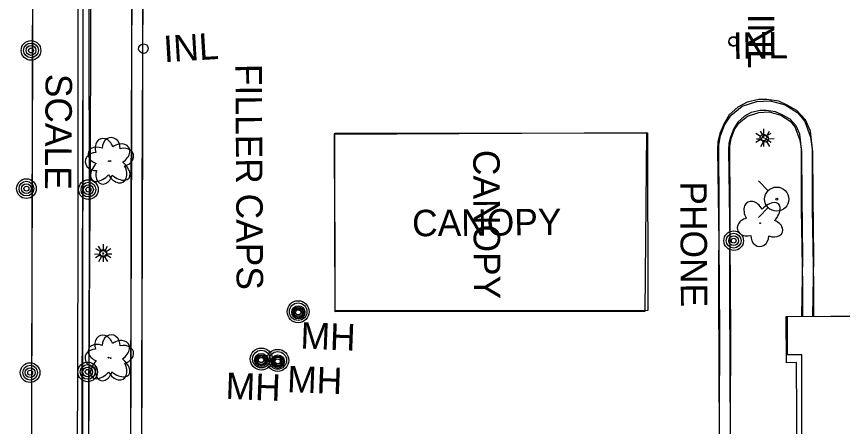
# Model space of a CAD drawing. Extents: x 588843 to 2552415, y 180129 to 269402.
# Drawn here: x 594396.9 to 594584.3, y 184767.3 to 184860.3 of the extents above; entities that cross this region are included whole.
import ezdxf

# ---------------------------------------------------------------- set-up
doc = ezdxf.new("R2010")
doc.units = 0
for name, color, linetype in [('Default', 7, 'Continuous'), ('E_BLD', 7, 'Continuous'), ('E_BLD_Dash', 7, 'Continuous'), ('E_BLD_HvyDash', 7, 'Continuous'), ('E_BLD_Text', 7, 'Continuous'), ('E_DRN', 7, 'Continuous'), ('E_DRN_Text', 7, 'Continuous'), ('E_DWY', 7, 'Continuous'), ('E_LAND_Vegetation', 7, 'Continuous'), ('E_LTG', 7, 'Continuous'), ('E_MISCPROP', 7, 'Continuous'), ('E_MISCPROP_Text', 7, 'Continuous'), ('E_UTL_AG_Text', 7, 'Continuous'), ('E_UTL_MH', 7, 'Continuous'), ('E_UTL_MH_Text', 7, 'Continuous'), ('E_UTL_WHydrant', 7, 'Continuous')]:
    doc.layers.add(name, color=color, linetype=linetype)

# ---------------------------------------------------------------- blocks, each defined once
blk = doc.blocks.new('SCAL')
at = {"layer": 'Default'}
blk.add_text('SCALE', height=12, dxfattribs=at).set_placement((-23.24, -6))
blk = doc.blocks.new('POLE')
at = {"layer": 'Default'}
for radius in [4.46, 3.35, 2.23, 1.12]:
    blk.add_circle((0, 0), radius, dxfattribs=at)
blk = doc.blocks.new('LPOL')
at = {"layer": 'Default'}
for p, q in [((-4, 0), (-1.5, 0)), ((-0.75, 1.3), (-2, 3.46)), ((0.75, 1.3), (2, 3.46)), ((1.5, 0), (4, 0)), ((-2, -3.46), (-0.75, -1.3)), ((2, -3.46), (0.75, -1.3))]:
    blk.add_line(p, q, dxfattribs=at)
for radius in [1.5, 1.5, 1.5, 0.125]:
    blk.add_circle((0, 0), radius, dxfattribs=at)
blk = doc.blocks.new('DTRE')
at = {"layer": 'Default'}
blk.add_circle((-0.18, 0), 0.183, dxfattribs=at)
for centre, major_axis, ratio in [((-1.87, 5.32), (1.36, -4.98), 0.782863), ((4.06, 2.74), (-5.27, -2.93), 0.691916), ((-5.87, 0.15), (4.93, -0.12), 0.832022), ((3.54, -3.71), (-5.01, 4.58), 0.560249), ((-2.49, -5.24), (1.8, 4.86), 0.716896)]:
    blk.add_ellipse(centre, major_axis=major_axis, ratio=ratio, start_param=1.570796, end_param=4.712389, dxfattribs=at)
blk = doc.blocks.new('CANOPY')
at = {"layer": 'E_BLD_Text'}
blk.add_text('CANOPY', height=12, dxfattribs=at).set_placement((-32.52, -6))
blk = doc.blocks.new('FILO')
at = {"layer": 'E_MISCPROP'}
for radius in [5, 4, 1.5]:
    blk.add_circle((0, 0), radius, dxfattribs=at)
blk = doc.blocks.new('FILT_4')
at = {"layer": 'E_MISCPROP_Text'}
blk.add_text('FILLER CAPS', height=12, dxfattribs=at).set_placement((10, -6))
blk = doc.blocks.new('PHONE')
at = {"layer": 'E_UTL_AG_Text'}
blk.add_text('PHONE', height=12, dxfattribs=at).set_placement((-26.35, -6))
blk = doc.blocks.new('HYD')
at = {"layer": 'Default'}
for p, q in [((-3.84, 3.84), (-8.32, 8.32)), ((3.84, 3.84), (8.32, 8.32))]:
    blk.add_line(p, q, dxfattribs=at)
for radius in [5.48, 0.42]:
    blk.add_circle((0, 0), radius, dxfattribs=at)
blk = doc.blocks.new('INLT_51')
at = {"layer": 'E_DRN_Text'}
blk.add_text('INL', height=12, dxfattribs=at).set_placement((-11.03, -6))
blk = doc.blocks.new('LPOL_4')
at = {"layer": 'E_LTG'}
for p, q in [((-13.1, 0), (-4.9, 0)), ((-2.5, 4.3), (-6.6, 11.4)), ((2.5, 4.3), (6.6, 11.4)), ((4.9, 0), (13.1, 0)), ((-6.6, -11.4), (-2.5, -4.3)), ((6.6, -11.4), (2.5, -4.3))]:
    blk.add_line(p, q, dxfattribs=at)
for radius in [4.92, 4.92, 4.92, 0.41]:
    blk.add_circle((0, 0), radius, dxfattribs=at)
blk = doc.blocks.new('INLT_32_2')
at = {"layer": 'E_DRN_Text'}
blk.add_text('INL', height=39.37, dxfattribs=at).set_placement((-36.2, -19.7))
blk = doc.blocks.new('MHO_3')
at = {"layer": 'E_UTL_MH'}
for centre, radius in [((0.3, -0.4), 9.84), ((0.3, -0.4), 7.98), ((0.2, -0.5), 6.35), ((0.1, -0.5), 3.97)]:
    blk.add_circle(centre, radius, dxfattribs=at)
blk = doc.blocks.new('MHT_3')
at = {"layer": 'E_UTL_MH_Text'}
blk.add_text('MH', height=39.37, dxfattribs=at).set_placement((-32.2, -19.7))
blk = doc.blocks.new('DTRE_4')
at = {"layer": 'E_LAND_Vegetation'}
blk.add_circle((-0.6, 0), 0.601, dxfattribs=at)
for centre, major_axis, ratio in [((-6.1, 17.5), (4.5, -16.3), 0.782863), ((13.3, 9), (-17.3, -9.6), 0.691916), ((-19.3, 0.5), (16.2, -0.4), 0.832022), ((11.6, -12.2), (-16.4, 15), 0.560249), ((-8.2, -17.2), (5.9, 15.9), 0.716896)]:
    blk.add_ellipse(centre, major_axis=major_axis, ratio=ratio, start_param=1.570796, end_param=4.712389, dxfattribs=at)
blk = doc.blocks.new('INLT_24_2')
at = {"layer": 'E_DRN_Text'}
blk.add_text('INL', height=39.37, dxfattribs=at).set_placement((-36.2, -19.7))
blk = doc.blocks.new('CANOPY_1')
at = {"layer": 'E_BLD_Text'}
blk.add_text('CANOPY', height=39.37, dxfattribs=at).set_placement((-106.7, -19.7))

msp = doc.modelspace()

# ---------------------------------------------------------------- linework, layer by layer
at = {"layer": 'E_BLD'}
msp.add_lwpolyline([(594608.14, 184723.58), (594571.85, 184723.33), (594571.78, 184734.03), (594574.21, 184734.05), (594573.89, 184781.74), (594571.61, 184781.72), (594571.54, 184792.23), (594601.99, 184792.44)], dxfattribs=at)
msp.add_lwpolyline([(594571.85, 184792.25), (594623.79, 184792.33), (594623.8, 184781.84), (594620.3, 184781.83), (594620.37, 184735.63), (594623.84, 184735.63), (594623.86, 184723.66), (594572.06, 184723.57), (594572.05, 184734.14), (594575.19, 184734.15), (594575.11, 184783.48), (594571.86, 184783.48)], close=True, dxfattribs=at)
at = {"layer": 'E_BLD_Dash'}
msp.add_lwpolyline([(594400.82, 184942.87), (594400.29, 184739.8), (594411.76, 184739.77), (594412.3, 184942.83)], close=True, dxfattribs=at)
at = {"layer": 'E_BLD_HvyDash'}
for points in [[(594412.17, 184942.93), (594411.81, 184740.07), (594400.36, 184739.94), (594400.8, 184943.06), (594412.17, 184942.93)], [(594469.12, 184833.63), (594539.86, 184833.96), (594539.49, 184793.32), (594469.23, 184793.25)], [(594469.2, 184793.54), (594469.17, 184833.83), (594540.12, 184833.88), (594540.15, 184793.6), (594469.2, 184793.54)]]:
    msp.add_lwpolyline(points, close=True, dxfattribs=at)
at = {"layer": 'E_DRN'}
for centre, radius in [((594559.66, 184854.73), 1.07), ((594559.58, 184854.56), 1.03)]:
    msp.add_circle(centre, radius, dxfattribs=at)
msp.add_ellipse((594425.73, 184853.02), major_axis=(0.31, 1.04), ratio=0.999083, dxfattribs=at)
at = {"layer": 'E_DWY'}
for points in [[(594421.96, 184675.59), (594415.82, 184703.87), (594411.73, 184723.08), (594411.26, 184727.36), (594410.68, 184734.11), (594410.96, 184807.45), (594410.92, 184870.64), (594411.16, 184901.91), (594411.17, 184939.88)], [(594424.41, 184676.12), (594418.27, 184704.4), (594414.2, 184723.48), (594413.75, 184727.6), (594413.18, 184734.21), (594413.46, 184807.45), (594413.42, 184870.63), (594413.66, 184901.89), (594413.67, 184939.88)], [(594447.77, 184915.17), (594448.18, 184897.65), (594448.19, 184895.9), (594447.53, 184894.66), (594446.24, 184893.39), (594445.15, 184892.78), (594441.01, 184892.63), (594423.19, 184892.62), (594423.1, 184870.83), (594423.02, 184855.19), (594423.02, 184838.7), (594422.95, 184807.7), (594422.8, 184779.99), (594422.79, 184749.18), (594422.83, 184730.02), (594429.93, 184730.14)], [(594450.27, 184915.23), (594450.68, 184897.69), (594450.7, 184895.29), (594449.56, 184893.15), (594447.76, 184891.37), (594445.84, 184890.3), (594441.06, 184890.13), (594425.68, 184890.12), (594425.6, 184870.82), (594425.52, 184855.18), (594425.52, 184838.7), (594425.45, 184807.69), (594425.3, 184779.99), (594425.29, 184749.18), (594425.29, 184748.72)], [(594425.33, 184748.66), (594425.31, 184753.72), (594425.45, 184777.31), (594425.48, 184799.41), (594425.47, 184820.54), (594425.6, 184851.34), (594425.7, 184865.36), (594425.84, 184889.86), (594440.33, 184889.96), (594445.07, 184890.02), (594447.12, 184890.68), (594448.91, 184892.09), (594450.28, 184894.21), (594450.81, 184896.05), (594450.4, 184915.27)], [(594413.61, 184904.03), (594413.83, 184876.2), (594413.68, 184831.02), (594413.36, 184779.01), (594413.27, 184758.12), (594413.16, 184745.67)], [(594480.38, 184678.45), (594480.29, 184693.97), (594480.25, 184702.88), (594479.6, 184707.44), (594477.45, 184712.65), (594474.89, 184716.54), (594470.69, 184720.3), (594467.18, 184722.78), (594463.03, 184724.57), (594459.67, 184725.43), (594457.35, 184725.79), (594442.77, 184725.45), (594442.43, 184727.18), (594441.4, 184729.04), (594440.03, 184730.04), (594438.57, 184730.59), (594422.92, 184730.39), (594422.81, 184753.72), (594422.95, 184777.32), (594422.98, 184799.41), (594422.97, 184820.54), (594423.1, 184851.35), (594423.2, 184865.37)], [(594577.61, 184792.27), (594577.86, 184805.61), (594577.71, 184819.34), (594577.63, 184829.57), (594577.08, 184834.25), (594575.94, 184836.85), (594574.02, 184838.97), (594571.8, 184840.21), (594569.91, 184841.07), (594567.2, 184841.5), (594565.35, 184841.44), (594562.73, 184840.85), (594560.63, 184839.75), (594558.67, 184837.95), (594557.49, 184836.05), (594556.53, 184833.72), (594556.09, 184831.85), (594555.99, 184830.12), (594556.28, 184809.04), (594556.41, 184788.79), (594556.38, 184768.7), (594556.43, 184744.56)], [(594556.33, 184817.03), (594556.3, 184831.08), (594556.67, 184833.3), (594557.65, 184835.83), (594559.08, 184837.91), (594561.6, 184839.96), (594564.92, 184840.98), (594567.95, 184841.19), (594571.35, 184840.22), (594574.19, 184838.47), (594575.77, 184836.49), (594577.09, 184832.89), (594577.48, 184830.29)], [(594575.1, 184792.26), (594575.36, 184805.62), (594575.21, 184819.32), (594575.14, 184829.42), (594574.64, 184833.59), (594573.81, 184835.47), (594572.44, 184836.99), (594570.67, 184837.98), (594569.18, 184838.66), (594567.04, 184839), (594565.67, 184838.95), (594563.6, 184838.48), (594562.08, 184837.69), (594560.62, 184836.34), (594559.72, 184834.9), (594558.92, 184832.95), (594558.57, 184831.49), (594558.49, 184830.06), (594558.78, 184809.06), (594558.91, 184788.79), (594558.88, 184768.7), (594558.93, 184744.56)], [(594558.83, 184817.04), (594558.8, 184830.87), (594559.1, 184832.63), (594559.88, 184834.66), (594560.94, 184836.2), (594562.8, 184837.71), (594565.39, 184838.51), (594567.68, 184838.67), (594570.33, 184837.91), (594572.51, 184836.57), (594573.57, 184835.25), (594574.66, 184832.27), (594575.01, 184829.92)], [(594575, 184830), (594574.99, 184816.61), (594575.24, 184799.24), (594575.29, 184792.25)], [(594577.5, 184830), (594577.49, 184816.63), (594577.74, 184799.26), (594577.79, 184792.26)], [(594544.47, 184702.12), (594549.24, 184706.8), (594551.61, 184709.57), (594553.35, 184712.76), (594554.6, 184715.8), (594555.55, 184719.12), (594556.13, 184722.81), (594556.5, 184743.59), (594556.45, 184764.47), (594556.3, 184797.59), (594556.33, 184817.04)], [(594546.22, 184700.34), (594551.06, 184705.1), (594553.67, 184708.14), (594555.61, 184711.68), (594556.96, 184714.98), (594557.99, 184718.57), (594558.63, 184722.59), (594559, 184743.58), (594558.95, 184764.48), (594558.8, 184797.59), (594558.83, 184817.04)]]:
    msp.add_lwpolyline(points, dxfattribs=at)

# ---------------------------------------------------------------- block references
at = {"layer": 'E_BLD_Text'}
for name, p, xscale, yscale, rotation in [('SCAL', (594406.47, 184835.67), 0.4999999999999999, 0.49999999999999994, -90.39935623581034), ('CANOPY', (594503.64, 184813.77), 0.49999999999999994, 0.4999999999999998, -89.6710262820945), ('CANOPY_1', (594502.95, 184813.56), 0.1524003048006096, 0.1524003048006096, 0.5167146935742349)]:
    msp.add_blockref(name, p, dxfattribs=dict(at, xscale=xscale, yscale=yscale, rotation=rotation))
at = {"layer": 'E_DRN_Text'}
for name, p, xscale, yscale, rotation in [('INLT_51', (594565.89, 184855.44), 0.5, 0.5, -89.98949477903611), ('INLT_32_2', (594435.79, 184853.25), 0.15240030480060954, 0.15240030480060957, 3.4338469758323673), ('INLT_24_2', (594564.98, 184853.74), 0.15240030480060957, 0.15240030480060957, 0.8014450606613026)]:
    msp.add_blockref(name, p, dxfattribs=dict(at, xscale=xscale, yscale=yscale, rotation=rotation))
at = {"layer": 'E_LAND_Vegetation'}
for name, p, xscale, yscale, rotation in [('DTRE_4', (594417.96, 184827.49), 0.15240030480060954, 0.15240030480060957, 3.4338469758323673), ('DTRE', (594418.29, 184827.42), 0.4999999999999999, 0.49999999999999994, -90.39935623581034), ('DTRE', (594565.68, 184813.5), 0.49999999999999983, 0.4999999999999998, 89.914494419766), ('DTRE_4', (594417.89, 184782.87), 0.15240030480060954, 0.15240030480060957, 3.4338469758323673), ('DTRE', (594418.3, 184782.66), 0.4999999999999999, 0.49999999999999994, -90.39935623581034)]:
    msp.add_blockref(name, p, dxfattribs=dict(at, xscale=xscale, yscale=yscale, rotation=rotation))
at = {"layer": 'E_LTG'}
for name, p, xscale, yscale, rotation in [('LPOL', (594566.43, 184832.81), 0.49999999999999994, 0.4999999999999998, -89.6710262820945), ('LPOL_4', (594566.81, 184832.55), 0.15240030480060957, 0.15240030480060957, 0.8014450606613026), ('LPOL_4', (594416.6, 184806.42), 0.15240030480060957, 0.15240030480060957, 0.8014450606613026), ('LPOL', (594416.6, 184806.63), 0.4999999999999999, 0.49999999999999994, -90.39935623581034)]:
    msp.add_blockref(name, p, dxfattribs=dict(at, xscale=xscale, yscale=yscale, rotation=rotation))
at = {"layer": 'E_MISCPROP'}
for name, p, xscale, yscale, rotation in [('POLE', (594400.23, 184852.6), 0.4999999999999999, 0.49999999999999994, -90.39935623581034), ('POLE', (594399.19, 184821.24), 0.4999999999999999, 0.49999999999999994, -90.39935623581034), ('POLE', (594413.26, 184821.02), 0.4999999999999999, 0.49999999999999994, -90.39935623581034), ('POLE', (594559.66, 184809.42), 0.49999999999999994, 0.4999999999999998, -89.6710262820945), ('FILO', (594460.84, 184793.31), 0.49999999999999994, 0.4999999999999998, -89.6710262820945), ('FILO', (594452.48, 184782.56), 0.49999999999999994, 0.4999999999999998, -89.6710262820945), ('FILO', (594456.21, 184782.26), 0.49999999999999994, 0.4999999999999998, -89.6710262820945), ('POLE', (594400.03, 184779.48), 0.4999999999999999, 0.49999999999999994, -90.39935623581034), ('POLE', (594413.08, 184779.64), 0.4999999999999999, 0.49999999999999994, -90.39935623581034)]:
    msp.add_blockref(name, p, dxfattribs=dict(at, xscale=xscale, yscale=yscale, rotation=rotation))
at = {"layer": 'E_MISCPROP_Text', "xscale": 0.49999999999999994, "yscale": 0.4999999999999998, "rotation": -89.6710262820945}
msp.add_blockref('FILT_4', (594449.57, 184854.54), dxfattribs=at)
at = {"layer": 'E_UTL_AG_Text', "xscale": 0.49999999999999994, "yscale": 0.4999999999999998, "rotation": -89.6710262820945}
msp.add_blockref('PHONE', (594550.6, 184809.7), dxfattribs=at)
at = {"layer": 'E_UTL_MH'}
for p, xscale, yscale, rotation in [((594460.85, 184793.23), 0.15240030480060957, 0.15240030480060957, -2.198250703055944), ((594452.41, 184782.4), 0.15240030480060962, 0.1524003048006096, -2.163912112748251), ((594456.17, 184782.07), 0.1524003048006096, 0.15240030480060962, -2.071693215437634)]:
    msp.add_blockref('MHO_3', p, dxfattribs=dict(at, xscale=xscale, yscale=yscale, rotation=rotation))
at = {"layer": 'E_UTL_MH_Text'}
for p, xscale, yscale, rotation in [((594466.31, 184787.75), 0.15240030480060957, 0.15240030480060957, -2.198250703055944), ((594463.28, 184777.87), 0.1524003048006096, 0.15240030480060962, -2.071693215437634), ((594449.32, 184776.33), 0.15240030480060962, 0.1524003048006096, -2.163912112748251)]:
    msp.add_blockref('MHT_3', p, dxfattribs=dict(at, xscale=xscale, yscale=yscale, rotation=rotation))
at = {"layer": 'E_UTL_WHydrant', "xscale": 0.49999999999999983, "yscale": 0.4999999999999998, "rotation": 89.914494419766}
msp.add_blockref('HYD', (594569.42, 184818.85), dxfattribs=at)

doc.saveas('drawing.dxf')
